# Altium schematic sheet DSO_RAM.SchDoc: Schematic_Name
size A4; CompanyName: University of Melbourne; Engineer: Your Name Here; DocumentNumber: 1; Revision: 0.1; SheetNumber: 1; SheetTotal: 1; Title_Project: Project_Title; StudentNo: Student No.
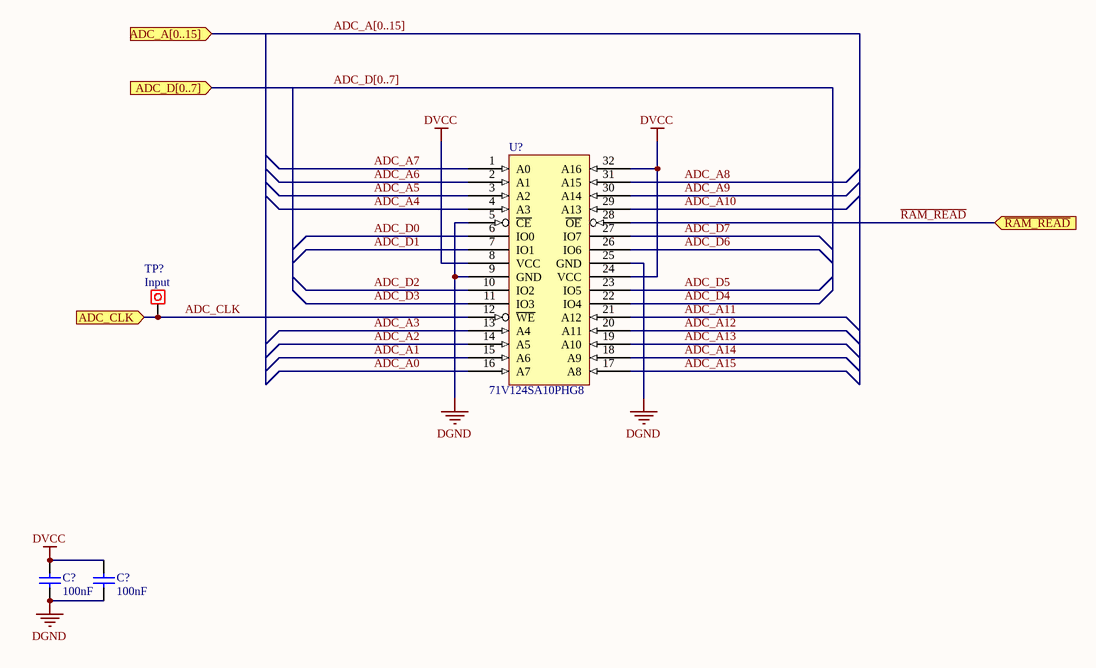
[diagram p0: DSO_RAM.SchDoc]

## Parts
(Parts that share a designator on the sheet are numbered #1, #2 ... from top to bottom, then left to right.)
C?#1  100nF  [0805C]
C?#2  100nF  [0805C]
TP?  INPUT  [Testpoin]
U?  71V124SA10PHG8  [TSOP-32]

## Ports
ADC_A[0..15] (in), ADC_CLK (in), ADC_D[0..7] (in), ~{RAM_READ} (in)

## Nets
DGND: C?#1.2 C?#2.2 U?.5(~{CE}) U?.9(GND) U?.25(GND)
DVCC: C?#1.1 C?#2.1 U?.8(VCC) U?.24(VCC) U?.32(A16)
ADC_A0: U?.16(A7)
ADC_A1: U?.15(A6)
ADC_A2: U?.14(A5)
ADC_A3: U?.13(A4)
ADC_A4: U?.4(A3)
ADC_A5: U?.3(A2)
ADC_A6: U?.2(A1)
ADC_A7: U?.1(A0)
ADC_A8: U?.31(A15)
ADC_A9: U?.30(A14)
ADC_A10: U?.29(A13)
ADC_A11: U?.21(A12)
ADC_A12: U?.20(A11)
ADC_A13: U?.19(A10)
ADC_A14: U?.18(A9)
ADC_A15: U?.17(A8)
ADC_CLK: TP?.1 U?.12(~{WE}) ; port ADC_CLK
ADC_D0: U?.6(IO0)
ADC_D1: U?.7(IO1)
ADC_D2: U?.10(IO2)
ADC_D3: U?.11(IO3)
ADC_D4: U?.22(IO4)
ADC_D5: U?.23(IO5)
ADC_D6: U?.26(IO6)
ADC_D7: U?.27(IO7)
~{RAM_READ}: U?.28(~{OE}) ; port ~{RAM_READ}

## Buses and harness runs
bus ADC_A[0..15] = port ADC_A[0..15]
bus ADC_D[0..7] = port ADC_D[0..7]

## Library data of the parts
C?#1 C?#2 = C: Capacitor; Reviewed by: RM - 2018/08/05
TP? = Test Point: Pad
U? = CY7C1019D: SRAM 128k x 8; Reviewed by: RM - 2018/08/05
